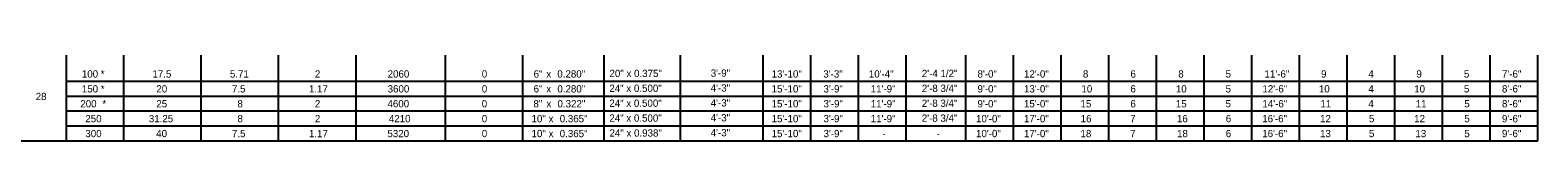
# Model space of a CAD drawing. Extents: x 3829340 to 3831660, y 499389 to 501171.
# Drawn here: x 3831039 to 3831660, y 500768 to 500803 of the extents above; entities that cross this region are included whole.
import ezdxf

# ---------------------------------------------------------------- set-up
doc = ezdxf.new("R2010")
doc.units = 0
doc.layers.add('TABULATION', color=7, linetype='Continuous')

msp = doc.modelspace()

# ---------------------------------------------------------------- linework, layer by layer
at = {"layer": 'TABULATION'}
for p, q in [((3831053.58, 500768.09), (3831053.58, 500803.31)), ((3831077.2, 500768.09), (3831077.2, 500803.31)), ((3831109.11, 500768.09), (3831109.11, 500803.31)), ((3831141.01, 500768.09), (3831141.01, 500803.31)), ((3831172.92, 500768.09), (3831172.92, 500803.31)), ((3831209.73, 500768.09), (3831209.73, 500803.31)), ((3831241.64, 500768.09), (3831241.64, 500803.31)), ((3831275.08, 500768.09), (3831275.08, 500803.31)), ((3831306.61, 500768.09), (3831306.61, 500803.31)), ((3831340.54, 500768.09), (3831340.54, 500803.31)), ((3831360.17, 500768.09), (3831360.17, 500803.31)), ((3831379.8, 500768.09), (3831379.8, 500803.31)), ((3831399.44, 500768.09), (3831399.44, 500803.31)), ((3831424.07, 500768.09), (3831424.07, 500803.31)), ((3831443.7, 500768.09), (3831443.7, 500803.31)), ((3831463.34, 500768.09), (3831463.34, 500803.31)), ((3831482.97, 500768.09), (3831482.97, 500803.31)), ((3831502.61, 500768.09), (3831502.61, 500803.31)), ((3831522.24, 500768.09), (3831522.24, 500803.31)), ((3831541.87, 500768.09), (3831541.87, 500803.31)), ((3831561.51, 500768.09), (3831561.51, 500803.31)), ((3831581.14, 500768.09), (3831581.14, 500803.31)), ((3831600.78, 500768.09), (3831600.78, 500803.31)), ((3831620.41, 500768.09), (3831620.41, 500803.31)), ((3831640.04, 500768.09), (3831640.04, 500803.31)), ((3831659.68, 500768.09), (3831659.68, 500803.31)), ((3831053.58, 500792.63), (3831659.68, 500792.63)), ((3831053.58, 500786.5), (3831659.68, 500786.5)), ((3831053.58, 500780.36), (3831659.68, 500780.36)), ((3831053.58, 500774.23), (3831659.68, 500774.23)), ((3831033.33, 500768.09), (3831659.68, 500768.09))]:
    msp.add_line(p, q, dxfattribs=at)

# ---------------------------------------------------------------- texts
for s, height, p in [('100', 3, (3831059.98, 500794.11)), (' *', 3, (3831066.64, 500794.11)), ('17.5', 3, (3831089.04, 500794.11)), ('5.71', 3, (3831120.94, 500794.11)), ('2', 3, (3831155.96, 500794.11)), ('2060', 3, (3831185.92, 500794.11)), ('0', 3, (3831224.69, 500794.11)), ('6"', 3, (3831246.04, 500794.11)), (' x', 3, (3831250.15, 500794.11)), (' 0.280"', 3, (3831254.71, 500794.11)), ('20" x 0.375"', 2.9996, (3831277.29, 500794.33)), ('3\'-9"', 3, (3831318.99, 500794.47)), ('13\'-10"', 3, (3831344.07, 500794.11)), ('3\'-3"', 3, (3831365.39, 500794.11)), ('10\'-4"', 3, (3831384.12, 500794.11)), ('2\'-4 1/2"', 3, (3831405.94, 500794.31)), ('8\'-0"', 3, (3831428.88, 500794.11)), ('12\'-0"', 3, (3831448.02, 500794.11)), ('8', 3, (3831472.3, 500794.11)), ('6', 3, (3831491.87, 500794.11)), ('8', 3, (3831511.57, 500794.11)), ('5', 3, (3831531.05, 500794.11)), ('11\'-6"', 3, (3831547.08, 500794.11)), ('9', 3, (3831570.39, 500794.11)), ('4', 3, (3831589.88, 500794.11)), ('9', 3, (3831609.66, 500794.11)), ('5', 3, (3831629.22, 500794.11)), ('7\'-6"', 3, (3831644.9, 500794.11)), ('28', 3, (3831040.96, 500784.84)), ('150', 3, (3831059.97, 500787.97)), (' *', 3, (3831066.66, 500787.97)), ('20', 3, (3831090.67, 500787.97)), ('7.5', 3, (3831121.79, 500787.97)), ('1.17', 3, (3831153.5, 500787.97)), ('3600', 3, (3831185.92, 500787.97)), ('0', 3, (3831224.69, 500787.97)), ('6"', 3, (3831246.04, 500787.97)), (' x', 3, (3831250.15, 500787.97)), (' 0.280"', 3, (3831254.71, 500787.97)), ('24" x 0.500"', 2.9996, (3831277.24, 500788.2)), ('4\'-3"', 3, (3831318.99, 500788.33)), ('15\'-10"', 3, (3831344.07, 500787.97)), ('3\'-9"', 3, (3831365.46, 500787.97)), ('11\'-9"', 3, (3831384.9, 500787.97)), ('2\'-8 3/4"', 3, (3831405.94, 500788.18)), ('9\'-0"', 3, (3831428.88, 500787.97)), ('13\'-0"', 3, (3831448.02, 500787.97)), ('10', 3, (3831471.69, 500787.97)), ('6', 3, (3831491.87, 500787.97)), ('10', 3, (3831510.58, 500787.97)), ('5', 3, (3831531.05, 500787.97)), ('12\'-6"', 3, (3831546.23, 500787.97)), ('10', 3, (3831569.48, 500787.97)), ('4', 3, (3831589.88, 500787.97)), ('10', 3, (3831608.75, 500787.97)), ('5', 3, (3831629.22, 500787.97)), ('8\'-6"', 3, (3831644.9, 500787.97)), ('200', 3, (3831059.34, 500781.84)), (' *', 3, (3831067.29, 500781.84)), ('25', 3, (3831090.65, 500781.84)), ('8', 3, (3831124.06, 500781.84)), ('2', 3, (3831155.96, 500781.84)), ('4600', 3, (3831185.85, 500781.84)), ('0', 3, (3831224.69, 500781.84)), ('8"', 3, (3831245.96, 500781.84)), (' x', 3, (3831250.21, 500781.84)), (' 0.322"', 3, (3831254.77, 500781.84)), ('24" x 0.500"', 2.9996, (3831277.24, 500782.06)), ('4\'-3"', 3, (3831318.99, 500782.2)), ('15\'-10"', 3, (3831344.07, 500781.84)), ('3\'-9"', 3, (3831365.46, 500781.84)), ('11\'-9"', 3, (3831384.9, 500781.84)), ('2\'-8 3/4"', 3, (3831405.94, 500782.04)), ('9\'-0"', 3, (3831428.88, 500781.84)), ('15\'-0"', 3, (3831448.02, 500781.84)), ('15', 3, (3831471.3, 500781.84)), ('6', 3, (3831491.86, 500781.84)), ('15', 3, (3831510.57, 500781.84)), ('5', 3, (3831531.05, 500781.84)), ('14\'-6"', 3, (3831546.23, 500781.84)), ('11', 3, (3831570.12, 500781.84)), ('4', 3, (3831589.88, 500781.84)), ('11', 3, (3831609.39, 500781.84)), ('5', 3, (3831629.38, 500781.84)), ('8\'-6"', 3, (3831644.9, 500781.84)), ('250', 3, (3831061.4, 500775.7)), ('31.25', 3, (3831087.55, 500775.7)), ('8', 3, (3831124.06, 500775.7)), ('2', 3, (3831155.96, 500775.7)), ('4210', 3, (3831186.41, 500775.7)), ('0', 3, (3831224.69, 500775.7)), ('10"', 3, (3831245.19, 500775.7)), (' x', 3, (3831251.12, 500775.7)), (' 0.365"', 3, (3831255.68, 500775.7)), ('24" x 0.500"', 2.9996, (3831277.24, 500775.93)), ('4\'-3"', 3, (3831318.99, 500776.06)), ('15\'-10"', 3, (3831344.07, 500775.7)), ('3\'-9"', 3, (3831365.46, 500775.7)), ('11\'-9"', 3, (3831384.9, 500775.7)), ('2\'-8 3/4"', 3, (3831405.94, 500775.91)), ('10\'-0"', 3, (3831428.27, 500775.7)), ('17\'-0"', 3, (3831448.02, 500775.7)), ('16', 3, (3831471.37, 500775.7)), ('7', 3, (3831491.77, 500775.7)), ('16', 3, (3831511.01, 500775.7)), ('6', 3, (3831531.14, 500775.7)), ('16\'-6"', 3, (3831546.16, 500775.7)), ('12', 3, (3831569.98, 500775.7)), ('5', 3, (3831590.11, 500775.7)), ('12', 3, (3831608.74, 500775.7)), ('5', 3, (3831629.38, 500775.7)), ('9\'-6"', 3, (3831644.9, 500775.7)), ('300', 3, (3831061.41, 500769.56)), ('40', 3, (3831090.59, 500769.56)), ('7.5', 3, (3831121.79, 500769.56)), ('1.17', 3, (3831153.5, 500769.56)), ('5320', 3, (3831185.83, 500769.56)), ('0', 3, (3831224.69, 500769.56)), ('10"', 3, (3831245.19, 500769.56)), (' x', 3, (3831251.12, 500769.56)), (' 0.365"', 3, (3831255.68, 500769.56)), ('24" x 0.938"', 2.9996, (3831277.29, 500769.79)), ('4\'-3"', 3, (3831318.99, 500769.93)), ('15\'-10"', 3, (3831344.07, 500769.56)), ('3\'-9"', 3, (3831365.46, 500769.56)), ('-', 3, (3831389.82, 500769.56)), ('-', 3, (3831411.96, 500769.56)), ('10\'-0"', 3, (3831428.27, 500769.56)), ('17\'-0"', 3, (3831448.02, 500769.56)), ('18', 3, (3831471.3, 500769.56)), ('7', 3, (3831491.77, 500769.56)), ('18', 3, (3831511.08, 500769.56)), ('6', 3, (3831531.12, 500769.56)), ('16\'-6"', 3, (3831546.16, 500769.56)), ('13', 3, (3831569.98, 500769.56)), ('5', 3, (3831590.11, 500769.56)), ('13', 3, (3831609.25, 500769.56)), ('5', 3, (3831629.38, 500769.56)), ('9\'-6"', 3, (3831644.9, 500769.56))]:
    msp.add_text(s, height=height, dxfattribs=at).set_placement(p)

doc.saveas('drawing.dxf')
